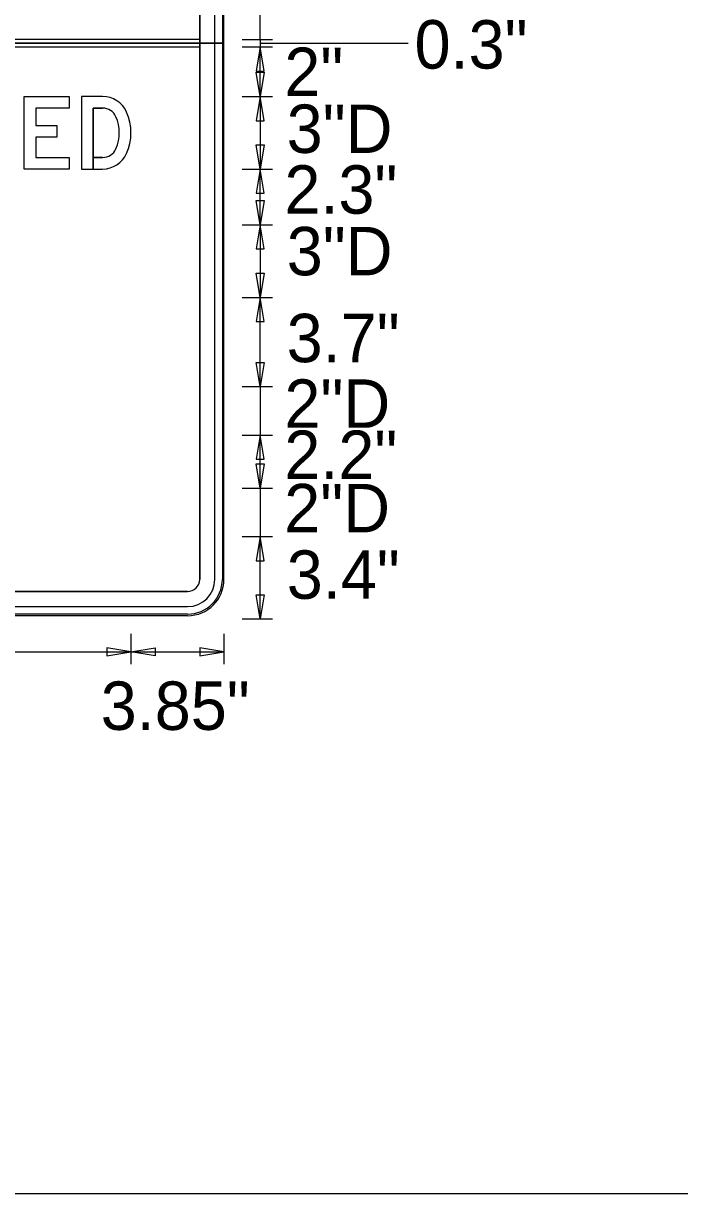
# Model space of a CAD drawing. Extents: x 17890484 to 17890754, y 17897495 to 17897992.
# Drawn here: x 17890617.92 to 17890625.45, y 17897572.57 to 17897586 of the extents above; entities that cross this region are included whole.
import ezdxf

# ---------------------------------------------------------------- set-up
doc = ezdxf.new("R2010")
doc.units = 0
for name, color, linetype in [('Default', 7, 'Continuous'), ('GSBWFill', 7, 'Continuous'), ('GSColorFill', 7, 'Continuous'), ('GSDims', 7, 'Continuous'), ('GSOutline', 7, 'Continuous'), ('SheetLinesMisc2_dp', 7, 'Continuous')]:
    doc.layers.add(name, color=color, linetype=linetype)

msp = doc.modelspace()

# ---------------------------------------------------------------- linework, layer by layer
at = {"layer": 'Default'}
msp.add_line((17890620.641, 17897585.771), (17890622.337, 17897585.771), dxfattribs=at)
at = {"layer": 'GSBWFill'}
for p, q in [((17890619.946, 17897590.452), (17890619.946, 17897579.618)), ((17890620.12, 17897579.618), (17890620.12, 17897590.452)), ((17890620.224, 17897579.618), (17890620.224, 17897590.452)), ((17890619.946, 17897585.814), (17890607.169, 17897585.814)), ((17890619.946, 17897585.728), (17890619.946, 17897585.814)), ((17890607.169, 17897585.728), (17890619.946, 17897585.728)), ((17890618.833, 17897584.459), (17890618.724, 17897584.459)), ((17890619.807, 17897579.479), (17890607.309, 17897579.479)), ((17890607.309, 17897579.306), (17890619.807, 17897579.306)), ((17890607.307, 17897579.202), (17890619.807, 17897579.202))]:
    msp.add_line(p, q, dxfattribs=at)
msp.add_lwpolyline([(17890618.449, 17897585.026), (17890618.066, 17897585.026), (17890618.066, 17897584.826), (17890618.308, 17897584.826), (17890618.308, 17897584.692), (17890618.066, 17897584.692), (17890618.066, 17897584.459), (17890618.449, 17897584.459), (17890618.449, 17897584.326), (17890617.932, 17897584.326), (17890617.932, 17897585.159), (17890618.449, 17897585.159)], close=True, dxfattribs=at)
for points in [[(17890618.833, 17897585.159), (17890618.591, 17897585.159), (17890618.591, 17897584.326), (17890618.724, 17897584.326), (17890618.724, 17897585.026), (17890618.833, 17897585.026)], [(17890618.724, 17897584.459), (17890618.724, 17897584.326), (17890618.833, 17897584.326)]]:
    msp.add_lwpolyline(points, dxfattribs=at)
for centre, radius, start, end in [((17890618.833, 17897584.859), 0.3, 23.9411, 90), ((17890618.833, 17897584.859), 0.167, 23.9411, 90), ((17890618.57, 17897584.742), 0.454, 336.0589, 23.9411), ((17890618.57, 17897584.742), 0.588, 336.0589, 23.9411), ((17890618.833, 17897584.626), 0.167, 270, 336.0589), ((17890618.833, 17897584.626), 0.3, 270, 336.0589), ((17890619.807, 17897579.618), 0.313, 270, 0), ((17890619.807, 17897579.618), 0.139, 270, 0), ((17890619.807, 17897579.618), 0.417, 270, 0)]:
    msp.add_arc(centre, radius, start, end, dxfattribs=at)
at = {"layer": 'GSColorFill'}
for p, q in [((17890619.946, 17897590.452), (17890619.946, 17897579.618)), ((17890620.12, 17897579.618), (17890620.12, 17897590.452)), ((17890620.207, 17897590.452), (17890620.207, 17897579.618)), ((17890620.224, 17897585.771), (17890620.224, 17897590.452)), ((17890620.224, 17897579.618), (17890620.224, 17897590.452)), ((17890619.946, 17897585.814), (17890607.169, 17897585.814)), ((17890619.946, 17897585.728), (17890619.946, 17897585.814)), ((17890620.224, 17897585.771), (17890606.891, 17897585.771)), ((17890606.891, 17897585.771), (17890620.224, 17897585.771)), ((17890607.169, 17897585.728), (17890619.946, 17897585.728)), ((17890620.224, 17897579.618), (17890620.224, 17897585.771)), ((17890618.833, 17897584.459), (17890618.724, 17897584.459)), ((17890619.807, 17897579.479), (17890607.309, 17897579.479)), ((17890607.309, 17897579.306), (17890619.807, 17897579.306)), ((17890607.307, 17897579.202), (17890619.807, 17897579.202)), ((17890619.807, 17897579.219), (17890607.308, 17897579.219)), ((17890607.308, 17897579.202), (17890619.807, 17897579.202))]:
    msp.add_line(p, q, dxfattribs=at)
msp.add_lwpolyline([(17890618.449, 17897585.026), (17890618.066, 17897585.026), (17890618.066, 17897584.826), (17890618.308, 17897584.826), (17890618.308, 17897584.692), (17890618.066, 17897584.692), (17890618.066, 17897584.459), (17890618.449, 17897584.459), (17890618.449, 17897584.326), (17890617.932, 17897584.326), (17890617.932, 17897585.159), (17890618.449, 17897585.159)], close=True, dxfattribs=at)
for points in [[(17890618.833, 17897585.159), (17890618.591, 17897585.159), (17890618.591, 17897584.326), (17890618.724, 17897584.326), (17890618.724, 17897585.026), (17890618.833, 17897585.026)], [(17890618.724, 17897584.459), (17890618.724, 17897584.326), (17890618.833, 17897584.326)]]:
    msp.add_lwpolyline(points, dxfattribs=at)
for centre, radius, start, end in [((17890618.833, 17897584.859), 0.3, 23.9411, 90), ((17890618.833, 17897584.859), 0.167, 23.9411, 90), ((17890618.57, 17897584.742), 0.454, 336.0589, 23.9411), ((17890618.57, 17897584.742), 0.588, 336.0589, 23.9411), ((17890618.833, 17897584.626), 0.167, 270, 336.0589), ((17890618.833, 17897584.626), 0.3, 270, 336.0589), ((17890619.807, 17897579.618), 0.417, 270, 0), ((17890619.807, 17897579.618), 0.313, 270, 0), ((17890619.807, 17897579.618), 0.139, 270, 0), ((17890619.807, 17897579.618), 0.417, 270, 0), ((17890619.807, 17897579.618), 0.399, 270, 0)]:
    msp.add_arc(centre, radius, start, end, dxfattribs=at)
at = {"layer": 'GSDims'}
for p, q in [((17890620.641, 17897585.814), (17890620.641, 17897586.244)), ((17890620.432, 17897585.814), (17890620.78, 17897585.814)), ((17890620.432, 17897585.814), (17890620.78, 17897585.814)), ((17890620.641, 17897585.814), (17890620.641, 17897585.728)), ((17890620.432, 17897585.728), (17890620.78, 17897585.728)), ((17890620.432, 17897585.728), (17890620.78, 17897585.728)), ((17890620.641, 17897585.159), (17890620.641, 17897585.728)), ((17890620.432, 17897585.159), (17890620.78, 17897585.159)), ((17890620.432, 17897585.159), (17890620.78, 17897585.159)), ((17890620.641, 17897585.159), (17890620.641, 17897584.326)), ((17890620.432, 17897584.326), (17890620.78, 17897584.326)), ((17890620.432, 17897584.326), (17890620.78, 17897584.326)), ((17890620.641, 17897583.687), (17890620.641, 17897584.326)), ((17890620.432, 17897583.687), (17890620.78, 17897583.687)), ((17890620.432, 17897583.687), (17890620.78, 17897583.687)), ((17890620.641, 17897583.687), (17890620.641, 17897582.853)), ((17890620.432, 17897582.853), (17890620.78, 17897582.853)), ((17890620.432, 17897582.853), (17890620.78, 17897582.853)), ((17890620.641, 17897581.83), (17890620.641, 17897582.853)), ((17890620.432, 17897581.83), (17890620.78, 17897581.83)), ((17890620.432, 17897581.83), (17890620.78, 17897581.83)), ((17890620.641, 17897581.83), (17890620.641, 17897581.274)), ((17890620.432, 17897581.274), (17890620.78, 17897581.274)), ((17890620.432, 17897581.274), (17890620.78, 17897581.274)), ((17890620.641, 17897580.665), (17890620.641, 17897581.274)), ((17890620.432, 17897580.665), (17890620.78, 17897580.665)), ((17890620.432, 17897580.665), (17890620.78, 17897580.665)), ((17890620.641, 17897580.665), (17890620.641, 17897580.109)), ((17890620.432, 17897580.109), (17890620.78, 17897580.109)), ((17890620.432, 17897580.109), (17890620.78, 17897580.109)), ((17890620.641, 17897579.164), (17890620.641, 17897580.109)), ((17890620.432, 17897579.164), (17890620.78, 17897579.164)), ((17890619.157, 17897578.993), (17890619.157, 17897578.646)), ((17890619.157, 17897578.993), (17890619.157, 17897578.646)), ((17890620.224, 17897578.993), (17890620.224, 17897578.646)), ((17890607.957, 17897578.785), (17890619.157, 17897578.785)), ((17890619.157, 17897578.785), (17890620.224, 17897578.785))]:
    msp.add_line(p, q, dxfattribs=at)
for points in [[(17890620.641, 17897585.728), (17890620.595, 17897585.45), (17890620.687, 17897585.45)], [(17890620.641, 17897585.159), (17890620.595, 17897585.437), (17890620.687, 17897585.437)], [(17890620.641, 17897585.159), (17890620.595, 17897584.881), (17890620.687, 17897584.881)], [(17890620.641, 17897584.326), (17890620.595, 17897584.603), (17890620.687, 17897584.603)], [(17890620.641, 17897584.326), (17890620.595, 17897584.048), (17890620.687, 17897584.048)], [(17890620.641, 17897583.687), (17890620.595, 17897583.965), (17890620.687, 17897583.965)], [(17890620.641, 17897583.687), (17890620.595, 17897583.409), (17890620.687, 17897583.409)], [(17890620.641, 17897582.853), (17890620.595, 17897583.131), (17890620.687, 17897583.131)], [(17890620.641, 17897582.853), (17890620.595, 17897582.576), (17890620.687, 17897582.576)], [(17890620.641, 17897581.83), (17890620.595, 17897582.108), (17890620.687, 17897582.108)], [(17890620.641, 17897581.274), (17890620.595, 17897580.997), (17890620.687, 17897580.997)], [(17890620.641, 17897580.665), (17890620.595, 17897580.942), (17890620.687, 17897580.942)], [(17890620.641, 17897580.109), (17890620.595, 17897579.831), (17890620.687, 17897579.831)], [(17890620.641, 17897579.164), (17890620.595, 17897579.442), (17890620.687, 17897579.442)], [(17890619.157, 17897578.785), (17890618.88, 17897578.831), (17890618.88, 17897578.739)], [(17890619.157, 17897578.785), (17890619.435, 17897578.831), (17890619.435, 17897578.739)], [(17890620.224, 17897578.785), (17890619.946, 17897578.831), (17890619.946, 17897578.739)]]:
    msp.add_lwpolyline(points, close=True, dxfattribs=at)
at = {"layer": 'GSOutline'}
for p, q in [((17890619.946, 17897579.618), (17890619.946, 17897590.452)), ((17890620.12, 17897579.618), (17890620.12, 17897590.452)), ((17890620.224, 17897579.618), (17890620.224, 17897590.452)), ((17890619.946, 17897585.814), (17890607.169, 17897585.814)), ((17890619.946, 17897585.728), (17890619.946, 17897585.814)), ((17890607.169, 17897585.728), (17890619.946, 17897585.728)), ((17890618.833, 17897585.159), (17890618.591, 17897585.159)), ((17890618.833, 17897585.026), (17890618.724, 17897585.026)), ((17890607.307, 17897579.479), (17890619.807, 17897579.479)), ((17890607.307, 17897579.306), (17890619.807, 17897579.306)), ((17890607.307, 17897579.202), (17890619.807, 17897579.202))]:
    msp.add_line(p, q, dxfattribs=at)
msp.add_lwpolyline([(17890618.449, 17897585.026), (17890618.066, 17897585.026), (17890618.066, 17897584.826), (17890618.308, 17897584.826), (17890618.308, 17897584.692), (17890618.066, 17897584.692), (17890618.066, 17897584.459), (17890618.449, 17897584.459), (17890618.449, 17897584.326), (17890617.932, 17897584.326), (17890617.932, 17897585.159), (17890618.449, 17897585.159)], close=True, dxfattribs=at)
for points in [[(17890618.591, 17897585.159), (17890618.591, 17897584.326), (17890618.833, 17897584.326)], [(17890618.724, 17897585.026), (17890618.724, 17897584.459), (17890618.833, 17897584.459)]]:
    msp.add_lwpolyline(points, dxfattribs=at)
for centre, radius, start, end in [((17890618.833, 17897584.859), 0.3, 23.9411, 90), ((17890618.833, 17897584.859), 0.167, 23.9411, 90), ((17890618.57, 17897584.742), 0.454, 336.0589, 23.9411), ((17890618.57, 17897584.742), 0.588, 336.0589, 23.9411), ((17890618.833, 17897584.626), 0.167, 270, 336.0589), ((17890618.833, 17897584.626), 0.3, 270, 336.0589), ((17890619.807, 17897579.618), 0.313, 270, 0), ((17890619.807, 17897579.618), 0.139, 270, 0), ((17890619.807, 17897579.618), 0.417, 270, 0)]:
    msp.add_arc(centre, radius, start, end, dxfattribs=at)
at = {"layer": 'SheetLinesMisc2_dp'}
msp.add_line((17890587.978, 17897572.57), (17890639.15, 17897572.57), dxfattribs=at)

# ---------------------------------------------------------------- texts
at = {"layer": 'GSDims'}
for s, p in [('0.3"', (17890622.411, 17897585.479)), ('2"', (17890620.917, 17897585.164)), ('3"D', (17890620.944, 17897584.511)), ('2.3"', (17890620.918, 17897583.814)), ('3"D', (17890620.945, 17897583.107)), ('3.7"', (17890620.944, 17897582.11)), ('2"D', (17890620.918, 17897581.357)), ('2.2"', (17890620.917, 17897580.77)), ('2"D', (17890620.916, 17897580.158)), ('3.4"', (17890620.945, 17897579.395)), ('3.85"', (17890618.811, 17897577.891))]:
    msp.add_text(s, height=0.5556, dxfattribs=at).set_placement(p)

doc.saveas('drawing.dxf')
